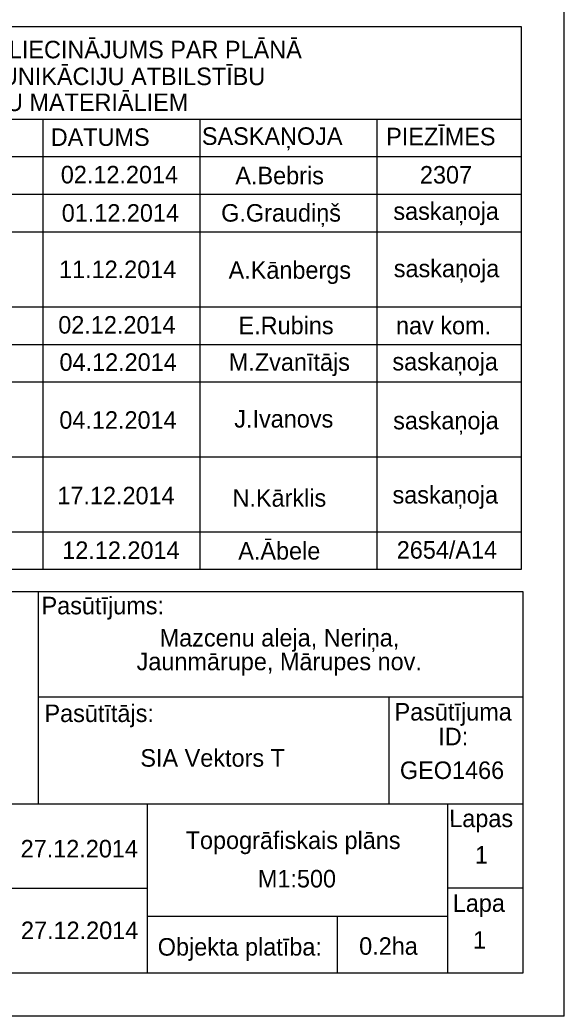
# Model space of a CAD drawing. Extents: x 496078 to 496285, y 304225 to 304369.
# Drawn here: x 496254.3 to 496285.3, y 304225.1 to 304282 of the extents above; entities that cross this region are included whole.
import ezdxf

# ---------------------------------------------------------------- set-up
doc = ezdxf.new("R2010")
doc.units = 0
doc.layers.add('RAMI_PLAN_####_TKST_#', color=7, linetype='Continuous')

msp = doc.modelspace()

# ---------------------------------------------------------------- linework, layer by layer
at = {"layer": 'RAMI_PLAN_####_TKST_#'}
for p, q in [((496285.321, 304225.145), (496285.321, 304369.101)), ((496221.306, 304281.594), (496282.865, 304281.594)), ((496282.865, 304281.594), (496282.865, 304250.614)), ((496282.865, 304276.294), (496221.306, 304276.294)), ((496255.581, 304276.294), (496255.581, 304250.614)), ((496264.532, 304276.294), (496264.532, 304250.614)), ((496274.641, 304276.294), (496274.641, 304250.614)), ((496282.865, 304274.152), (496221.306, 304274.152)), ((496282.865, 304272.009), (496221.306, 304272.009)), ((496282.865, 304269.867), (496221.306, 304269.867)), ((496282.865, 304265.583), (496221.306, 304265.583)), ((496282.865, 304263.441), (496221.306, 304263.441)), ((496282.865, 304261.301), (496221.306, 304261.301)), ((496282.865, 304257.021), (496221.306, 304257.021)), ((496282.865, 304252.741), (496221.306, 304252.741)), ((496282.865, 304250.614), (496221.306, 304250.614)), ((496221.637, 304249.368), (496282.959, 304249.367)), ((496255.312, 304249.367), (496255.312, 304237.26)), ((496282.959, 304249.367), (496282.959, 304227.594)), ((496255.312, 304243.35), (496282.959, 304243.35)), ((496275.328, 304243.35), (496275.328, 304237.26)), ((496221.637, 304237.26), (496282.959, 304237.26)), ((496261.537, 304237.26), (496261.537, 304227.594)), ((496278.674, 304237.26), (496278.675, 304227.594)), ((496261.537, 304232.424), (496221.637, 304232.424)), ((496278.675, 304232.463), (496282.959, 304232.463)), ((496261.537, 304230.84), (496278.674, 304230.84)), ((496272.37, 304230.839), (496272.37, 304227.594)), ((496282.959, 304227.594), (496221.637, 304227.594)), ((496285.321, 304225.145), (496089.321, 304225.145))]:
    msp.add_line(p, q, dxfattribs=at)

# ---------------------------------------------------------------- texts
for s, p in [(' EKSPLUATĒJOŠO ORGANIZĀCIJU APLIECINĀJUMS PAR PLĀNĀ', (496229.262, 304279.776)), (' UZRĀDĪTO APAKŠZEMJU KOMUNIKĀCIJU ATBILSTĪBU', (496233.272, 304278.247)), (' ŠO ORGANIZĀCIJU ARHĪVU MATERIĀLIEM', (496236.387, 304276.768)), ('DATUMS', (496256.027, 304274.78)), ('SASKAŅOJA', (496264.652, 304274.839)), ('PIEZĪMES', (496275.168, 304274.814)), ('A.Bebris', (496266.562, 304272.591)), ('2307', (496277.095, 304272.632)), ('01.12.2014', (496256.654, 304270.457)), ('G.Graudiņš', (496265.752, 304270.461)), ('saskaņoja', (496275.579, 304270.559)), ('saskaņoja', (496275.603, 304267.288)), ('11.12.2014', (496256.501, 304267.239)), ('A.Kānbergs', (496266.176, 304267.2)), ('02.12.2014', (496256.457, 304264.073)), ('E.Rubins', (496266.743, 304264.04)), ('nav kom.', (496275.729, 304264.035)), ('M.Zvanītājs', (496266.19, 304261.953)), ('saskaņoja', (496275.525, 304261.973)), ('04.12.2014', (496256.519, 304258.647)), ('J.Ivanovs', (496266.501, 304258.712)), ('saskaņoja', (496275.569, 304258.614)), ('17.12.2014', (496256.405, 304254.335)), ('N.Kārklis', (496266.399, 304254.2)), ('saskaņoja', (496275.531, 304254.379)), ('A.Ābele', (496266.728, 304251.183)), ('2654/A14', (496275.772, 304251.237))]:
    msp.add_text(s, height=1, dxfattribs=at).set_placement(p)
for s, rotation, p in [('02.12.2014', 359.9987, (496256.602, 304272.642)), ('04.12.2014', 359.9987, (496256.526, 304261.949)), ('12.12.2014', 359.9987, (496256.685, 304251.22)), ('Pasūtījums:', 0.024, (496255.503, 304248.06)), ('Mazcenu aleja, Neriņa, ', 0, (496262.241, 304246.225)), ('Jaunmārupe, Mārupes nov. ', 0, (496260.928, 304244.871)), ('Pasūtītājs:', 0.024, (496255.671, 304241.916)), ('Pasūtījuma', 0.024, (496275.648, 304241.999)), ('ID:', 0.024, (496278.142, 304240.591)), ('SIA Vektors T', 0, (496261.141, 304239.37)), ('GEO1466', 0, (496275.953, 304238.669)), ('Lapas', 0.024, (496278.768, 304235.922)), ('Topogrāfiskais plāns', 359.9996, (496263.726, 304234.676)), ('27.12.2014', 0, (496254.31, 304234.194)), ('1', 0.024, (496280.233, 304233.839)), ('M1:500', 0, (496267.847, 304232.482)), ('Lapa', 0.024, (496278.97, 304231.089)), ('27.12.2014', 0, (496254.329, 304229.536)), ('0.2ha', 0, (496273.627, 304228.641)), ('1', 0.024, (496280.121, 304228.987)), ('Objekta platība:', 0.024, (496262.134, 304228.593))]:
    msp.add_text(s, height=1, rotation=rotation, dxfattribs=at).set_placement(p)

doc.saveas('drawing.dxf')
